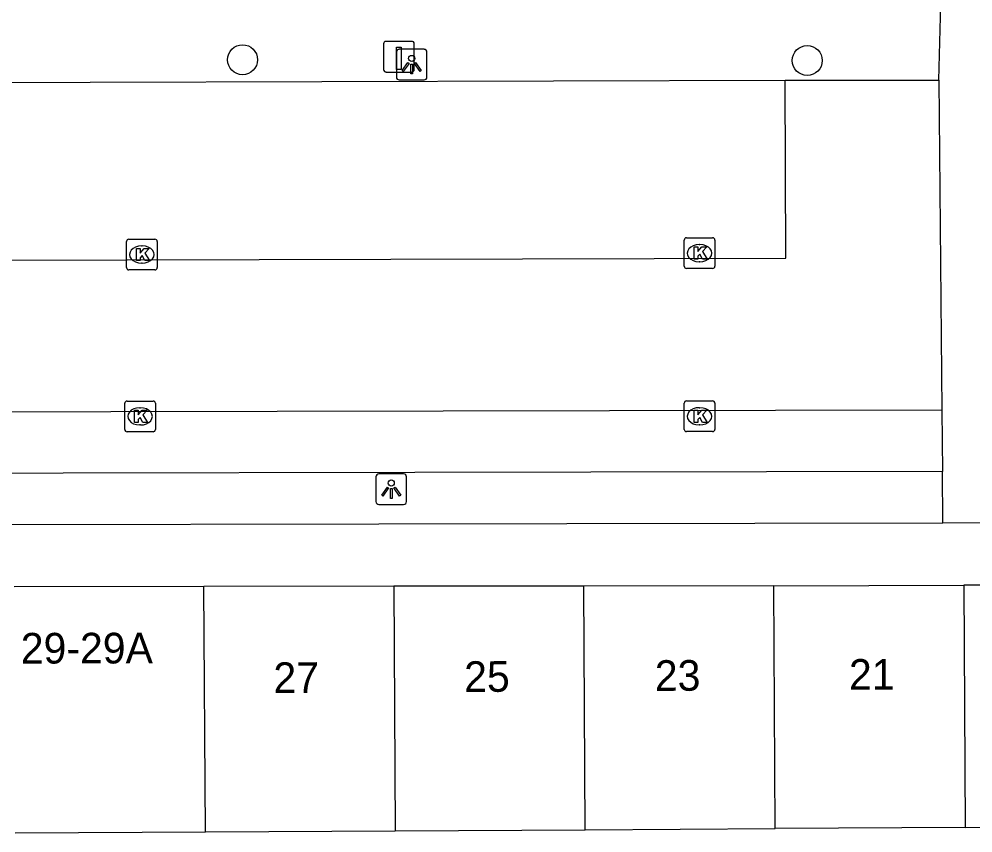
# Model space of a CAD drawing. Extents: x 160732 to 162105, y 387428 to 388479.
# Drawn here: x 161187.37 to 161218.49, y 387942.47 to 387969.02 of the extents above; entities that cross this region are included whole.
import ezdxf

# ---------------------------------------------------------------- set-up
doc = ezdxf.new("R2010")
doc.units = 0
for name, color, linetype in [('IMGEO_Boom', 7, 'Continuous'), ('IMGEO_Kolk', 7, 'Continuous'), ('IMGEO_Laadpaal', 7, 'Continuous'), ('IMGEO_Lichtpunt', 7, 'Continuous'), ('IMGEO_Pand', 7, 'Continuous'), ('IMGEO_Pand_nummerreeks', 7, 'Continuous'), ('IMGEO_Rijbaan_lokaal_open', 7, 'Continuous'), ('IMGEO_Voetpad_open', 7, 'Continuous')]:
    doc.layers.add(name, color=color, linetype=linetype)

msp = doc.modelspace()

# ---------------------------------------------------------------- linework, layer by layer
at = {"layer": 'IMGEO_Boom'}
for centre in [(161194.661, 387967.696), (161213.087, 387967.67)]:
    msp.add_circle(centre, 0.489, dxfattribs=at)
at = {"layer": 'IMGEO_Kolk'}
for p, q in [((161190.876, 387960.913), (161190.876, 387961.765)), ((161190.951, 387961.839), (161191.803, 387961.839)), ((161191.877, 387961.765), (161191.877, 387960.913)), ((161209.072, 387960.959), (161209.072, 387961.811)), ((161209.147, 387961.885), (161209.999, 387961.885)), ((161210.073, 387961.811), (161210.073, 387960.959)), ((161191.364, 387961.619), (161191.389, 387961.619)), ((161209.56, 387961.665), (161209.585, 387961.665)), ((161191.387, 387961.059), (161191.362, 387961.059)), ((161209.583, 387961.105), (161209.558, 387961.105)), ((161191.803, 387960.839), (161190.951, 387960.839)), ((161209.999, 387960.885), (161209.147, 387960.885)), ((161190.816, 387955.632), (161190.816, 387956.484)), ((161190.891, 387956.558), (161191.743, 387956.558)), ((161191.817, 387956.484), (161191.817, 387955.632)), ((161209.072, 387955.635), (161209.072, 387956.487)), ((161209.147, 387956.561), (161209.999, 387956.561)), ((161210.073, 387956.487), (161210.073, 387955.635)), ((161191.304, 387956.338), (161191.329, 387956.338)), ((161209.56, 387956.341), (161209.585, 387956.341)), ((161191.327, 387955.778), (161191.302, 387955.778)), ((161209.583, 387955.781), (161209.558, 387955.781)), ((161191.743, 387955.558), (161190.891, 387955.558)), ((161209.999, 387955.561), (161209.147, 387955.561))]:
    msp.add_line(p, q, dxfattribs=at)
for points in [[(161190.876, 387960.913), (161190.876, 387961.765)], [(161190.951, 387961.839), (161191.803, 387961.839)], [(161191.877, 387961.765), (161191.877, 387960.913)], [(161209.072, 387960.959), (161209.072, 387961.811)], [(161209.147, 387961.885), (161209.999, 387961.885)], [(161210.073, 387961.811), (161210.073, 387960.959)], [(161191.197, 387961.539), (161191.32, 387961.539), (161191.32, 387961.388), (161191.45, 387961.539), (161191.614, 387961.539), (161191.468, 387961.388), (161191.621, 387961.139), (161191.469, 387961.139), (161191.384, 387961.303), (161191.32, 387961.236), (161191.32, 387961.139), (161191.197, 387961.139), (161191.197, 387961.539)], [(161209.393, 387961.585), (161209.516, 387961.585), (161209.516, 387961.434), (161209.646, 387961.585), (161209.81, 387961.585), (161209.664, 387961.434), (161209.817, 387961.185), (161209.665, 387961.185), (161209.58, 387961.349), (161209.516, 387961.282), (161209.516, 387961.185), (161209.393, 387961.185), (161209.393, 387961.585)], [(161191.803, 387960.839), (161190.951, 387960.839)], [(161209.999, 387960.885), (161209.147, 387960.885)], [(161190.816, 387955.632), (161190.816, 387956.484)], [(161190.891, 387956.558), (161191.743, 387956.558)], [(161191.817, 387956.484), (161191.817, 387955.632)], [(161209.072, 387955.635), (161209.072, 387956.487)], [(161209.147, 387956.561), (161209.999, 387956.561)], [(161210.073, 387956.487), (161210.073, 387955.635)], [(161191.137, 387956.258), (161191.26, 387956.258), (161191.26, 387956.107), (161191.39, 387956.258), (161191.554, 387956.258), (161191.408, 387956.107), (161191.561, 387955.858), (161191.409, 387955.858), (161191.324, 387956.022), (161191.26, 387955.955), (161191.26, 387955.858), (161191.137, 387955.858), (161191.137, 387956.258)], [(161209.393, 387956.261), (161209.516, 387956.261), (161209.516, 387956.11), (161209.646, 387956.261), (161209.81, 387956.261), (161209.664, 387956.11), (161209.817, 387955.861), (161209.665, 387955.861), (161209.58, 387956.025), (161209.516, 387955.958), (161209.516, 387955.861), (161209.393, 387955.861), (161209.393, 387956.261)], [(161191.743, 387955.558), (161190.891, 387955.558)], [(161209.999, 387955.561), (161209.147, 387955.561)]]:
    msp.add_lwpolyline(points, dxfattribs=at)
for centre, start, end in [((161190.953, 387961.763), 91.552, 178.448), ((161190.953, 387961.763), 91.552, 178.448), ((161191.801, 387961.763), 1.552, 88.448), ((161191.801, 387961.763), 1.552, 88.448), ((161209.149, 387961.809), 91.552, 178.448), ((161209.149, 387961.809), 91.552, 178.448), ((161209.997, 387961.809), 1.552, 88.448), ((161209.997, 387961.809), 1.552, 88.448), ((161190.953, 387960.915), 181.552, 268.448), ((161190.953, 387960.915), 181.552, 268.448), ((161191.801, 387960.915), 271.552, 358.448), ((161191.801, 387960.915), 271.552, 358.448), ((161209.149, 387960.961), 181.552, 268.448), ((161209.149, 387960.961), 181.552, 268.448), ((161209.997, 387960.961), 271.552, 358.448), ((161209.997, 387960.961), 271.552, 358.448), ((161190.893, 387956.482), 91.552, 178.448), ((161190.893, 387956.482), 91.552, 178.448), ((161191.741, 387956.482), 1.552, 88.448), ((161191.741, 387956.482), 1.552, 88.448), ((161209.149, 387956.485), 91.552, 178.448), ((161209.149, 387956.485), 91.552, 178.448), ((161209.997, 387956.485), 1.552, 88.448), ((161209.997, 387956.485), 1.552, 88.448), ((161190.893, 387955.634), 181.552, 268.448), ((161190.893, 387955.634), 181.552, 268.448), ((161191.741, 387955.634), 271.552, 358.448), ((161191.741, 387955.634), 271.552, 358.448), ((161209.149, 387955.637), 181.552, 268.448), ((161209.149, 387955.637), 181.552, 268.448), ((161209.997, 387955.637), 271.552, 358.448), ((161209.997, 387955.637), 271.552, 358.448)]:
    msp.add_arc(centre, 0.0765, start, end, dxfattribs=at)
for centre, major_axis, ratio, start_param, end_param in [((161191.363, 387961.339), (-0.387, 0.002), 0.722429, 4.712389, 7.853982), ((161191.388, 387961.339), (-0.39, 0.002), 0.717154, 1.570796, 4.712389), ((161209.559, 387961.385), (-0.387, 0.002), 0.722429, 4.712389, 7.853982), ((161209.584, 387961.385), (-0.39, 0.002), 0.717154, 1.570796, 4.712389), ((161191.303, 387956.058), (-0.387, 0.002), 0.722429, 4.712389, 7.853982), ((161191.328, 387956.058), (-0.39, 0.002), 0.717154, 1.570796, 4.712389), ((161209.559, 387956.061), (-0.387, 0.002), 0.722429, 4.712389, 7.853982), ((161209.584, 387956.061), (-0.39, 0.002), 0.717154, 1.570796, 4.712389)]:
    msp.add_ellipse(centre, major_axis=major_axis, ratio=ratio, start_param=start_param, end_param=end_param, dxfattribs=at)
at = {"layer": 'IMGEO_Laadpaal'}
for p, q in [((161199.264, 387968.211), (161199.264, 387967.37)), ((161199.264, 387968.211), (161199.264, 387967.37)), ((161200.18, 387968.295), (161199.339, 387968.295)), ((161200.18, 387968.295), (161199.339, 387968.295)), ((161200.264, 387967.379), (161200.264, 387968.22)), ((161200.264, 387967.379), (161200.264, 387968.22)), ((161199.348, 387967.295), (161200.189, 387967.295)), ((161199.348, 387967.295), (161200.189, 387967.295))]:
    msp.add_line(p, q, dxfattribs=at)
msp.add_lwpolyline([(161199.679, 387968.108), (161199.839, 387968.108), (161199.839, 387967.375), (161199.679, 387967.375), (161199.679, 387968.108)], dxfattribs=at)
for centre, start, end in [((161199.342, 387968.217), 92.4484, 184.2845), ((161199.342, 387968.217), 92.4484, 184.2845), ((161200.186, 387968.217), 2.4484, 94.2845), ((161200.186, 387968.217), 2.4484, 94.2845), ((161199.342, 387967.373), 182.4484, 274.2845), ((161199.342, 387967.373), 182.4484, 274.2845), ((161200.186, 387967.373), 272.4484, 4.2845), ((161200.186, 387967.373), 272.4484, 4.2845)]:
    msp.add_arc(centre, 0.0779, start, end, dxfattribs=at)
at = {"layer": 'IMGEO_Lichtpunt'}
for p, q in [((161199.681, 387967.94), (161199.681, 387967.133)), ((161199.681, 387967.94), (161199.681, 387967.133)), ((161200.583, 387968.035), (161199.775, 387968.035)), ((161200.583, 387968.035), (161199.775, 387968.035)), ((161200.677, 387967.133), (161200.677, 387967.94)), ((161200.677, 387967.133), (161200.677, 387967.94)), ((161199.775, 387967.039), (161200.583, 387967.039)), ((161199.775, 387967.039), (161200.583, 387967.039)), ((161199.015, 387954.085), (161199.015, 387953.278)), ((161199.015, 387954.085), (161199.015, 387953.278)), ((161199.917, 387954.18), (161199.109, 387954.18)), ((161199.917, 387954.18), (161199.109, 387954.18)), ((161200.011, 387953.278), (161200.011, 387954.085)), ((161200.011, 387953.278), (161200.011, 387954.085)), ((161199.109, 387953.184), (161199.917, 387953.184)), ((161199.109, 387953.184), (161199.917, 387953.184))]:
    msp.add_line(p, q, dxfattribs=at)
for points in [[(161200.055, 387967.604), (161200.094, 387967.576), (161199.906, 387967.314), (161199.868, 387967.341), (161200.055, 387967.604)], [(161200.267, 387967.576), (161200.305, 387967.603), (161200.492, 387967.341), (161200.453, 387967.313), (161200.267, 387967.576)], [(161200.157, 387967.556), (161200.204, 387967.556), (161200.204, 387967.234), (161200.157, 387967.234), (161200.157, 387967.556)], [(161199.389, 387953.749), (161199.428, 387953.721), (161199.24, 387953.459), (161199.202, 387953.486), (161199.389, 387953.749)], [(161199.491, 387953.701), (161199.538, 387953.701), (161199.538, 387953.379), (161199.491, 387953.379), (161199.491, 387953.701)], [(161199.601, 387953.721), (161199.639, 387953.748), (161199.826, 387953.486), (161199.787, 387953.458), (161199.601, 387953.721)]]:
    msp.add_lwpolyline(points, dxfattribs=at)
for centre in [(161200.18, 387967.738), (161199.514, 387953.883)]:
    msp.add_circle(centre, 0.0994, dxfattribs=at)
for centre, start, end in [((161199.775, 387967.94), 90, 180), ((161199.775, 387967.94), 90, 180), ((161200.583, 387967.94), 0, 90), ((161200.583, 387967.94), 0, 90), ((161199.775, 387967.133), 180, 270), ((161199.775, 387967.133), 180, 270), ((161200.583, 387967.133), 270, 0), ((161200.583, 387967.133), 270, 360), ((161199.109, 387954.085), 90, 180), ((161199.109, 387954.085), 90, 180), ((161199.917, 387954.085), 0, 90), ((161199.917, 387954.085), 0, 90), ((161199.109, 387953.278), 180, 270), ((161199.109, 387953.278), 180, 270), ((161199.917, 387953.278), 270, 0), ((161199.917, 387953.278), 270, 360)]:
    msp.add_arc(centre, 0.0946, start, end, dxfattribs=at)
at = {"layer": 'IMGEO_Pand'}
for points in [[(161193.403, 387950.502), (161187.204, 387950.491)], [(161199.602, 387950.513), (161193.403, 387950.502)], [(161193.447, 387942.501), (161193.403, 387950.502)], [(161205.801, 387950.523), (161199.602, 387950.513)], [(161199.602, 387950.513), (161199.646, 387942.535)], [(161212, 387950.534), (161205.801, 387950.523)], [(161205.845, 387942.57), (161205.801, 387950.523)], [(161212, 387950.534), (161218.199, 387950.545)], [(161212.044, 387942.605), (161212, 387950.534)], [(161224.399, 387950.555), (161218.199, 387950.545)], [(161218.199, 387950.545), (161218.243, 387942.639)], [(161187.247, 387942.466), (161193.447, 387942.501)], [(161193.447, 387942.501), (161199.646, 387942.535)], [(161199.646, 387942.535), (161205.845, 387942.57)], [(161205.845, 387942.57), (161212.044, 387942.605)], [(161218.243, 387942.639), (161212.044, 387942.605)], [(161218.243, 387942.639), (161224.443, 387942.674)]]:
    msp.add_lwpolyline(points, dxfattribs=at)
at = {"layer": 'IMGEO_Rijbaan_lokaal_open'}
for points in [[(161173.705, 387961.122), (161212.393, 387961.222), (161212.367, 387967.026)], [(161212.367, 387967.026), (161217.376, 387967.03)], [(161217.376, 387967.03), (161217.48, 387956.261)], [(161217.48, 387956.261), (161168.663, 387956.165)]]:
    msp.add_lwpolyline(points, dxfattribs=at)
at = {"layer": 'IMGEO_Voetpad_open'}
for points in [[(161217.376, 387967.03), (161217.515, 387971.998), (161217.501, 387972.088)], [(161174.563, 387966.923), (161212.367, 387967.026)], [(161217.48, 387956.261), (161217.496, 387954.255)], [(161217.496, 387954.255), (161171.575, 387954.168), (161170.974, 387954.445), (161169.968, 387955.554)], [(161217.507, 387952.589), (161217.496, 387954.255)], [(161168.418, 387952.495), (161217.507, 387952.589)], [(161217.507, 387952.589), (161243.083, 387952.638)]]:
    msp.add_lwpolyline(points, dxfattribs=at)

# ---------------------------------------------------------------- texts
at = {"layer": 'IMGEO_Pand_nummerreeks'}
for s, rotation, p in [('29-29A', 0.1031, (161187.425, 387947.991)), ('27', 0.3207, (161195.671, 387947.03)), ('25', 0.3207, (161201.894, 387947.065)), ('23', 0.3207, (161208.116, 387947.099)), ('21', 0.3207, (161214.451, 387947.135))]:
    msp.add_text(s, height=1, rotation=rotation, dxfattribs=at).set_placement(p)

doc.saveas('drawing.dxf')
